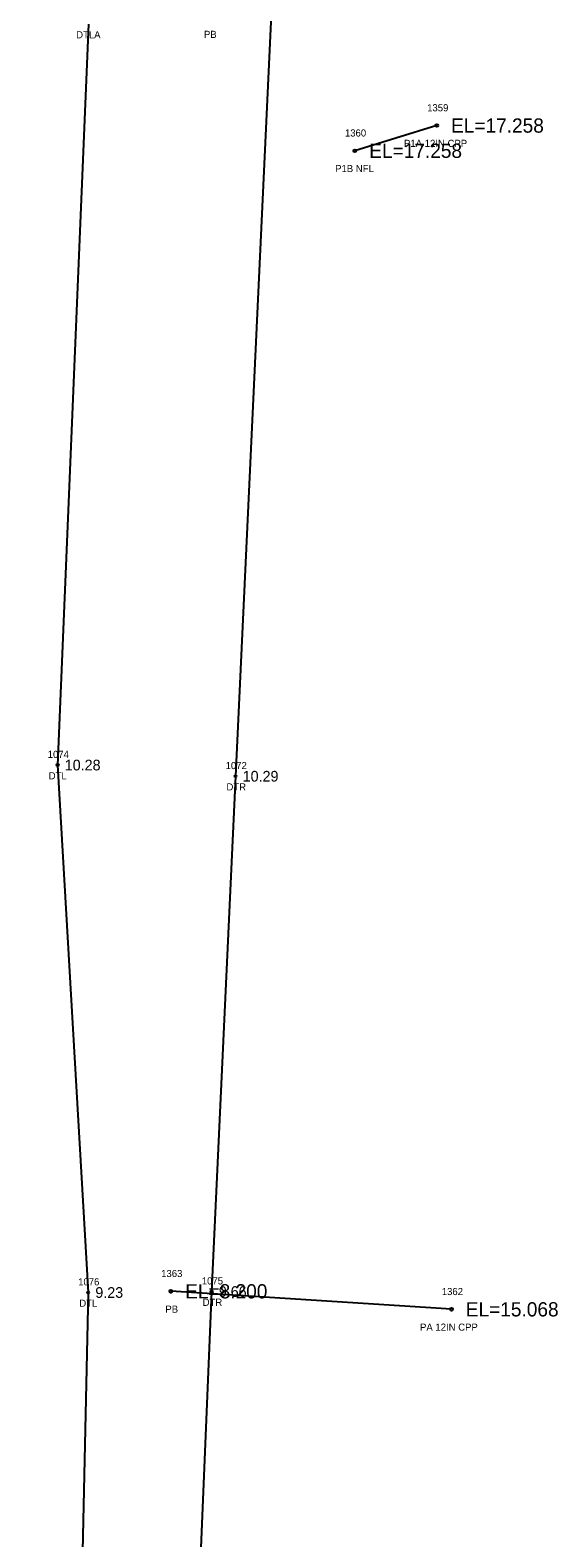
# Model space of a CAD drawing. Extents: x 2072307 to 2072993, y 127574 to 129736.
# Drawn here: x 2072397.2 to 2072471.2, y 129261.4 to 129473 of the extents above; entities that cross this region are included whole.
import ezdxf

# ---------------------------------------------------------------- set-up
doc = ezdxf.new("R2010")
doc.units = 0
for name, color, linetype in [('RD_EX_DR_Pipe', 7, 'Continuous'), ('RD_EX_DR_Pipe_txCode', 7, 'Continuous'), ('RD_EX_H2O', 7, 'Continuous'), ('RD_EX_H2O_txCode', 7, 'Continuous'), ('RD_EX_TX_H2O_ELEV', 7, 'Continuous'), ('RD_SMD_Locator', 7, 'Continuous'), ('RD_TX_Pipe_ElevEX', 7, 'Continuous')]:
    doc.layers.add(name, color=color, linetype=linetype)

msp = doc.modelspace()

# ---------------------------------------------------------------- linework, layer by layer
at = {"layer": 'RD_EX_DR_Pipe'}
for p, q in [((2072454.23, 129459.65), (2072442.76, 129456.11)), ((2072456.3, 129293.46), (2072416.95, 129295.99))]:
    msp.add_line(p, q, dxfattribs=at)
at = {"layer": 'RD_EX_H2O'}
for points in [[(2072405.39, 129473.9), (2072401.06, 129369.87), (2072405.35, 129295.82), (2072402.29, 129156.96), (2072397.22, 129166.67)], [(2072430.99, 129475.23), (2072426.01, 129368.3), (2072422.66, 129295.95), (2072416.7, 129153.3), (2072414.39, 129056.34)]]:
    msp.add_lwpolyline(points, dxfattribs=at)
at = {"layer": 'RD_SMD_Locator'}
for centre, radius in [((2072454.23, 129459.65), 0.2), ((2072442.76, 129456.11), 0.2), ((2072401.06, 129369.87), 0.15), ((2072426.01, 129368.3), 0.15), ((2072405.35, 129295.82), 0.15), ((2072416.95, 129295.99), 0.2), ((2072422.66, 129295.95), 0.15), ((2072456.3, 129293.46), 0.2)]:
    msp.add_circle(centre, radius, dxfattribs=at)

# ---------------------------------------------------------------- texts
at = {"layer": 'RD_EX_DR_Pipe_txCode'}
for s, p in [('PB', (2072421.58, 129471.95)), ('1359', (2072452.88, 129461.65)), ('1360', (2072441.35, 129458.11)), ('P1A 12IN CPP', (2072449.64, 129456.65)), ('P1B NFL', (2072439.98, 129453.11)), ('1363', (2072415.58, 129297.99)), ('1362', (2072454.93, 129295.46)), ('PB', (2072416.17, 129292.99)), ('PA 12IN CPP', (2072451.88, 129290.46))]:
    msp.add_text(s, height=1, dxfattribs=at).set_placement(p)
at = {"layer": 'RD_EX_H2O_txCode'}
for s, p in [('DTLA', (2072403.66, 129471.9)), ('DTLA', (2072403.66, 129471.9)), ('1074', (2072399.67, 129370.87)), ('1072', (2072424.62, 129369.3)), ('DTL', (2072399.81, 129367.87)), ('DTR', (2072424.74, 129366.3)), ('1076', (2072403.94, 129296.82)), ('1075', (2072421.28, 129296.95)), ('DTL', (2072404.1, 129293.82)), ('DTR', (2072421.4, 129293.95))]:
    msp.add_text(s, height=1, dxfattribs=at).set_placement(p)
at = {"layer": 'RD_EX_TX_H2O_ELEV'}
for s, p in [('10.28', (2072402.06, 129369.12)), ('10.29', (2072427.01, 129367.55)), ('9.23', (2072406.35, 129295.07)), ('9.66', (2072423.66, 129295.2))]:
    msp.add_text(s, height=1.5, dxfattribs=at).set_placement(p)
at = {"layer": 'RD_TX_Pipe_ElevEX'}
for s, p in [('EL=17.258', (2072456.23, 129458.65)), ('EL=17.258', (2072444.76, 129455.11)), ('EL=8.200', (2072418.95, 129294.99)), ('EL=15.068', (2072458.3, 129292.46))]:
    msp.add_text(s, height=2, dxfattribs=at).set_placement(p)

doc.saveas('drawing.dxf')
